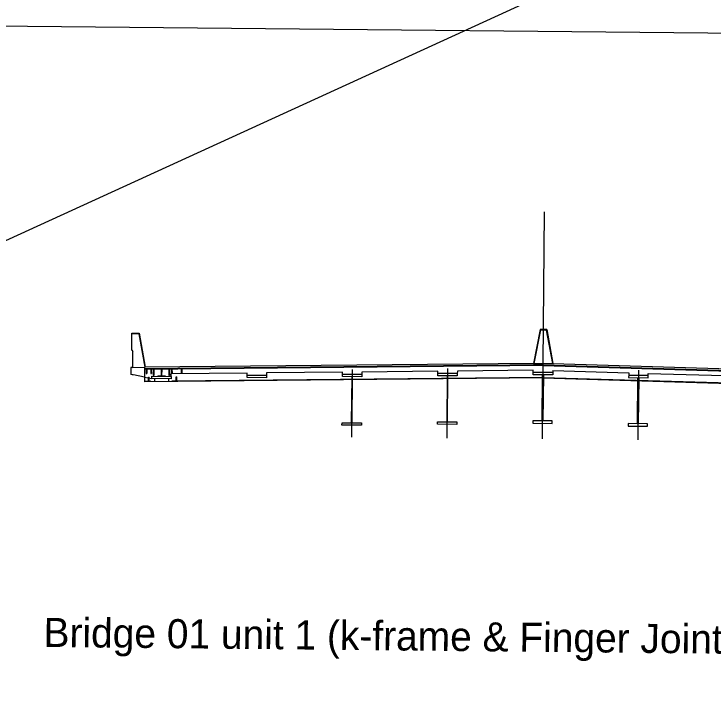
# Model space of a CAD drawing. Extents: x 632047 to 632524, y 378118 to 378491.
# Drawn here: x 632388.7 to 632460.8, y 378377 to 378447.3 of the extents above; entities that cross this region are included whole.
import ezdxf

# ---------------------------------------------------------------- set-up
doc = ezdxf.new("R2010")
doc.units = 0
for name, color, linetype in [('B_Boring', 7, 'Continuous'), ('B_Boring Annot', 7, 'Continuous'), ('R_Border_Divider', 7, 'Continuous'), ('R_Proposed Const Limits Cut', 7, 'Continuous'), ('R_Road Edge of Shoulder', 7, 'Continuous'), ('R_Shade Removal', 7, 'Continuous'), ('USACE_Easement', 7, 'Continuous')]:
    doc.layers.add(name, color=color, linetype=linetype)

msp = doc.modelspace()

# ---------------------------------------------------------------- linework, layer by layer
at = {"layer": 'B_Boring'}
for p, q in [((632442.949, 378414.793), (632442.247, 378411.3)), ((632442.983, 378414.751), (632442.29, 378411.299)), ((632443.615, 378414.786), (632442.949, 378414.793)), ((632442.983, 378414.751), (632443.58, 378414.745)), ((632443.58, 378414.745), (632444.205, 378411.28)), ((632443.615, 378414.786), (632444.247, 378411.28)), ((632400.859, 378414.37), (632400.86, 378414.412)), ((632400.859, 378414.37), (632401.575, 378414.363)), ((632400.86, 378414.412), (632401.609, 378414.404)), ((632401.575, 378414.363), (632402.199, 378410.897)), ((632401.609, 378414.404), (632402.241, 378410.898)), ((632442.247, 378411.3), (632402.158, 378410.897)), ((632402.158, 378410.897), (632402.173, 378409.397)), ((632443.246, 378411.143), (632402.16, 378410.73)), ((632443.246, 378411.143), (632484.232, 378409.916)), ((632444.247, 378411.28), (632484.237, 378410.082)), ((632443.233, 378409.81), (632402.173, 378409.397)), ((632443.233, 378409.81), (632484.192, 378408.583))]:
    msp.add_line(p, q, dxfattribs=at)
for points in [[(632422.569, 378410.185), (632424.569, 378410.165), (632424.566, 378409.915), (632422.566, 378409.935)], [(632432.403, 378410.284), (632434.403, 378410.264), (632434.401, 378410.014), (632432.401, 378410.034)], [(632442.238, 378410.382), (632444.238, 378410.363), (632444.236, 378410.113), (632442.236, 378410.132)], [(632412.734, 378410.086), (632414.734, 378410.066), (632414.731, 378409.816), (632412.731, 378409.836)], [(632423.608, 378409.924), (632423.524, 378409.925), (632423.477, 378405.175), (632423.561, 378405.175)], [(632433.443, 378410.023), (632433.359, 378410.024), (632433.312, 378405.274), (632433.395, 378405.273)], [(632443.194, 378410.123), (632443.277, 378410.122), (632443.23, 378405.372), (632443.147, 378405.373)], [(632454.069, 378410.068), (632452.069, 378410.088), (632452.067, 378409.838), (632454.066, 378409.818)], [(632453.025, 378409.829), (632453.108, 378409.828), (632453.061, 378405.078), (632452.978, 378405.079)], [(632422.519, 378405.185), (632424.519, 378405.165), (632424.516, 378404.915), (632422.516, 378404.935)], [(632432.354, 378405.284), (632434.354, 378405.264), (632434.351, 378405.014), (632432.351, 378405.034)], [(632444.188, 378405.363), (632442.188, 378405.383), (632442.186, 378405.133), (632444.186, 378405.113)], [(632454.019, 378405.068), (632452.019, 378405.088), (632452.017, 378404.838), (632454.017, 378404.818)]]:
    msp.add_lwpolyline(points, close=True, dxfattribs=at)
at = {"layer": 'B_Boring Annot'}
for p, q in [((632400.842, 378412.662), (632400.86, 378414.412)), ((632400.842, 378412.662), (632400.966, 378412.535)), ((632400.949, 378410.885), (632400.966, 378412.535)), ((632400.949, 378410.885), (632400.741, 378410.883)), ((632400.741, 378410.883), (632400.734, 378410.174)), ((632400.931, 378410.134), (632400.734, 378410.174)), ((632400.931, 378410.134), (632400.984, 378410.167)), ((632401.014, 378410.118), (632400.984, 378410.167)), ((632402.168, 378409.884), (632401.014, 378410.118))]:
    msp.add_line(p, q, dxfattribs=at)
at = {"layer": 'R_Border_Divider'}
for p, q in [((632400.949, 378410.885), (632402.158, 378410.897)), ((632442.247, 378411.3), (632444.247, 378411.28)), ((632404.899, 378409.967), (632404.901, 378410.216)), ((632412.736, 378410.295), (632404.901, 378410.216)), ((632412.734, 378410.086), (632412.736, 378410.295)), ((632414.736, 378410.315), (632414.734, 378410.066)), ((632422.571, 378410.394), (632414.736, 378410.315)), ((632422.569, 378410.185), (632422.571, 378410.394)), ((632424.569, 378410.165), (632422.569, 378410.185)), ((632424.571, 378410.414), (632424.569, 378410.165)), ((632432.405, 378410.493), (632424.571, 378410.414)), ((632432.403, 378410.284), (632432.405, 378410.493)), ((632434.403, 378410.264), (632432.403, 378410.284)), ((632434.406, 378410.513), (632434.403, 378410.264)), ((632442.24, 378410.592), (632434.406, 378410.513)), ((632442.238, 378410.382), (632442.24, 378410.592)), ((632444.238, 378410.363), (632442.238, 378410.382)), ((632444.24, 378410.572), (632444.238, 378410.363)), ((632444.24, 378410.572), (632452.072, 378410.337)), ((632452.072, 378410.337), (632452.069, 378410.088)), ((632454.069, 378410.068), (632454.071, 378410.277)), ((632454.071, 378410.277), (632461.902, 378410.043)), ((632402.168, 378409.884), (632402.897, 378409.737)), ((632414.734, 378410.066), (632412.734, 378410.086)), ((632452.069, 378410.088), (632454.069, 378410.068))]:
    msp.add_line(p, q, dxfattribs=at)
at = {"layer": 'R_Proposed Const Limits Cut'}
for p, q in [((632443.245, 378411.089), (632402.16, 378410.676)), ((632443.245, 378411.089), (632484.231, 378409.862)), ((632402.323, 378410.684), (632402.327, 378410.268)), ((632402.327, 378410.268), (632402.389, 378410.268)), ((632402.385, 378410.685), (632402.389, 378410.268)), ((632402.823, 378410.689), (632402.827, 378410.273)), ((632402.827, 378410.273), (632402.889, 378410.273)), ((632402.885, 378410.69), (632402.889, 378410.273)), ((632403.073, 378410.692), (632403.067, 378410.069)), ((632403.135, 378410.692), (632403.129, 378410.068)), ((632403.885, 378410.693), (632403.879, 378410.019)), ((632403.927, 378410.694), (632403.92, 378410.018)), ((632404.677, 378410.695), (632404.671, 378410.053)), ((632404.74, 378410.695), (632404.733, 378410.052)), ((632404.927, 378410.697), (632404.931, 378410.28)), ((632404.994, 378410.281), (632404.931, 378410.28)), ((632404.99, 378410.698), (632404.994, 378410.281)), ((632405.927, 378410.707), (632405.931, 378410.29)), ((632405.994, 378410.291), (632405.931, 378410.29)), ((632405.989, 378410.708), (632405.994, 378410.291)), ((632402.822, 378409.458), (632402.173, 378409.451)), ((632402.581, 378409.455), (632402.577, 378409.872)), ((632402.577, 378409.872), (632402.639, 378409.872)), ((632402.643, 378409.456), (632402.639, 378409.872)), ((632402.822, 378409.458), (632402.821, 378409.405)), ((632403.067, 378410.069), (632403.129, 378410.068)), ((632403.177, 378409.734), (632403.187, 378409.407)), ((632403.524, 378410.022), (632403.879, 378410.019)), ((632403.524, 378410.022), (632403.524, 378409.981)), ((632403.92, 378410.018), (632404.274, 378410.015)), ((632404.274, 378410.015), (632404.274, 378409.973)), ((632404.626, 378409.72), (632404.623, 378409.421)), ((632404.733, 378410.052), (632404.671, 378410.053)), ((632404.968, 378409.479), (632404.967, 378409.423)), ((632443.233, 378409.864), (632404.968, 378409.479)), ((632405.431, 378409.9), (632405.494, 378409.901)), ((632405.435, 378409.484), (632405.431, 378409.9)), ((632405.498, 378409.484), (632405.494, 378409.901)), ((632443.233, 378409.864), (632484.194, 378408.637))]:
    msp.add_line(p, q, dxfattribs=at)
msp.add_lwpolyline([(632402.899, 378409.987), (632404.899, 378409.967), (632404.896, 378409.717), (632402.897, 378409.737)], close=True, dxfattribs=at)
at = {"layer": 'R_Road Edge of Shoulder'}
msp.add_line((632443.17, 378403.509), (632443.403, 378426.931), dxfattribs=at)
at = {"layer": 'R_Shade Removal'}
for p, q in [((632423.574, 378410.686), (632423.504, 378403.705)), ((632433.408, 378410.785), (632433.337, 378403.607)), ((632453.074, 378410.589), (632453.003, 378403.411))]:
    msp.add_line(p, q, dxfattribs=at)
at = {"layer": 'USACE_Easement'}
msp.add_line((632523.679, 378486.131), (632046.82, 378267.872), dxfattribs=at)
msp.add_lwpolyline([(632379.538, 378446.195), (632491.765, 378445.079), (632491.027, 378370.898), (632378.8, 378372.014)], close=True, dxfattribs=at)

# ---------------------------------------------------------------- texts
msp.add_text('Bridge 01 unit 1 (k-frame & Finger Joint no design)', height=3, rotation=359.43036, dxfattribs=at).set_placement((632391.737, 378382.067))

doc.saveas('drawing.dxf')
